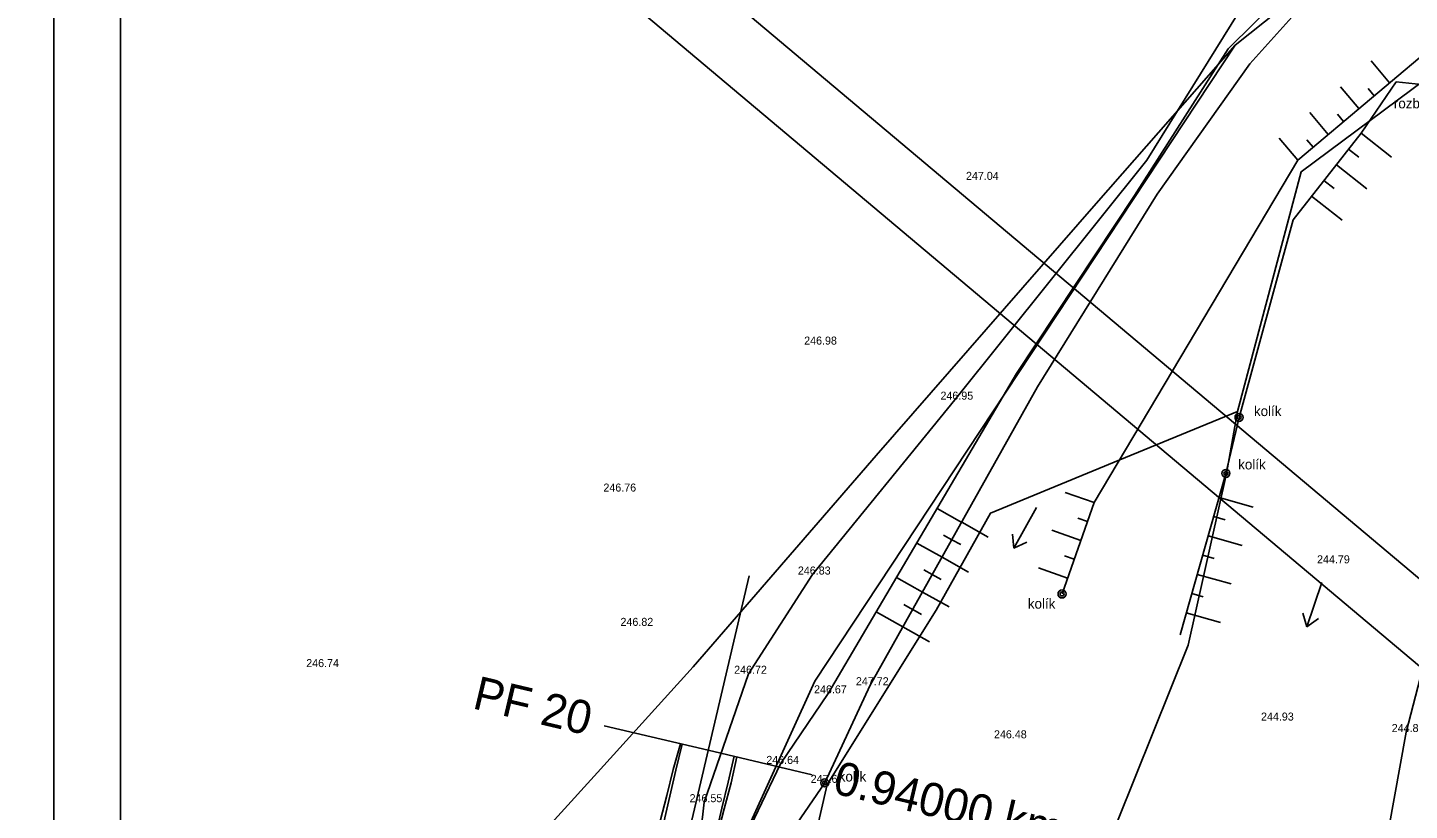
# Model space of a CAD drawing. Extents: x -555887 to -552101, y -1100251 to -1096546.
# Drawn here: x -554315.6 to -554212, y -1096894.5 to -1096835.8 of the extents above; entities that cross this region are included whole.
import ezdxf

# ---------------------------------------------------------------- set-up
doc = ezdxf.new("R2010")
doc.units = 0
for name, color, linetype in [('PARCELY_VHO', 7, 'Continuous'), ('POLYGONY_SITUACE_PF', 7, 'Continuous'), ('POLYGONY_SITUACE_PF_POPISY', 7, 'Continuous'), ('POLYGONY_SITUACE_PO', 7, 'Continuous'), ('ram_VC2', 7, 'Continuous'), ('ram_VC6', 7, 'Continuous'), ('Výškopis', 7, 'Continuous'), ('ZSST', 7, 'Continuous'), ('zájem', 7, 'Continuous')]:
    doc.layers.add(name, color=color, linetype=linetype)

msp = doc.modelspace()

# ---------------------------------------------------------------- linework, layer by layer
at = {"layer": 'PARCELY_VHO'}
for points in [[(-554130.46, -1097180.06), (-554159.17, -1097101.34), (-554159.64, -1097082.93), (-554163.72, -1097067.19), (-554173.74, -1097050.79), (-554190.63, -1097034.96), (-554197.16, -1097028.05), (-554217.46, -1096987.98), (-554225.33, -1096977.64), (-554234.21, -1096944.26), (-554236.99, -1096909.92), (-554235.22, -1096898.62), (-554228.6, -1096882.13), (-554225.73, -1096869.26), (-554224.9, -1096864.61), (-554220.11, -1096846.63), (-554200.4, -1096831.93), (-554179.17, -1096807.62), (-554142.08, -1096773.53), (-554110.69, -1096747.36), (-554089.18, -1096729.49)], [(-554235.26, -1097250.21), (-554222.33, -1097095.1), (-554222.18, -1097088.53), (-554223.59, -1097078.8), (-554226.63, -1097069.37), (-554233.34, -1097058.26), (-554245.88, -1097042.06), (-554250.33, -1097033.26), (-554252.75, -1097025.27), (-554253.64, -1097013.94), (-554251.14, -1096944.55), (-554252.47, -1096936.15), (-554254.99, -1096928.04), (-554262.23, -1096914.12), (-554265.12, -1096907.97), (-554264.18, -1096901.52), (-554256.59, -1096884.82), (-554225.08, -1096837.14), (-554208.2, -1096823.7)], [(-554200.4, -1096831.93), (-554220.11, -1096846.63), (-554224.9, -1096864.61), (-554233.29, -1096868.06), (-554243.42, -1096872.22), (-554247.48, -1096879.5), (-554255.66, -1096892.57), (-554260.45, -1096913.44), (-554248.68, -1096931.61), (-554247, -1096951.09), (-554248.74, -1096969.23), (-554247.82, -1097012.49), (-554234.69, -1097042.48), (-554228.63, -1097050.04), (-554218.79, -1097074.22), (-554216.52, -1097103.52), (-554219.47, -1097120.44), (-554219.42, -1097159.44)]]:
    msp.add_lwpolyline(points, dxfattribs=at)
at = {"layer": 'POLYGONY_SITUACE_PF'}
for p, q in [((-554272.37, -1096888.17), (-554264.58, -1096890)), ((-554264.58, -1096890), (-554256.79, -1096891.84))]:
    msp.add_line(p, q, dxfattribs=at)
at = {"layer": 'POLYGONY_SITUACE_PO'}
for p, q in [((-554268.72, -1096907.59), (-554261.5, -1096876.93)), ((-554267.2, -1096891.44), (-554266.65, -1096889.52)), ((-554266.99, -1096891.49), (-554266.53, -1096889.55)), ((-554266.99, -1096891.49), (-554266.53, -1096889.55)), ((-554263.09, -1096892.41), (-554262.63, -1096890.46)), ((-554263.09, -1096892.41), (-554262.63, -1096890.46)), ((-554262.86, -1096892.46), (-554262.43, -1096890.51)), ((-554267.67, -1096893.39), (-554267.2, -1096891.44)), ((-554267.44, -1096893.44), (-554266.99, -1096891.49)), ((-554267.44, -1096893.44), (-554266.99, -1096891.49)), ((-554263.55, -1096894.36), (-554263.09, -1096892.41)), ((-554263.55, -1096894.36), (-554263.09, -1096892.41)), ((-554263.39, -1096894.39), (-554262.86, -1096892.46)), ((-554268.17, -1096895.32), (-554267.67, -1096893.39)), ((-554267.9, -1096895.39), (-554267.44, -1096893.44)), ((-554267.9, -1096895.39), (-554267.44, -1096893.44)), ((-554264.01, -1096896.3), (-554263.55, -1096894.36)), ((-554264.01, -1096896.3), (-554263.55, -1096894.36)), ((-554263.88, -1096896.33), (-554263.39, -1096894.39))]:
    msp.add_line(p, q, dxfattribs=at)
at = {"layer": 'ram_VC2'}
for points in [[(-554114.88, -1096958.27), (-554342.13, -1096767.04), (-555018.18, -1097570.44), (-554790.93, -1097761.67)], [(-554121.93, -1096958.88), (-554341.52, -1096774.09), (-555011.14, -1097569.84), (-554791.54, -1097754.63)]]:
    msp.add_lwpolyline(points, close=True, dxfattribs=at)
for points in [[(-554114.88, -1096958.27), (-554342.13, -1096767.04), (-555018.18, -1097570.44), (-554790.93, -1097761.67), (-554114.88, -1096958.27)], [(-554791.54, -1097754.63), (-555011.14, -1097569.84), (-554341.52, -1096774.09), (-554121.93, -1096958.88), (-554791.54, -1097754.63)]]:
    msp.add_lwpolyline(points, dxfattribs=at)
at = {"layer": 'ram_VC6'}
for points in [[(-553956.64, -1096765.72), (-554313.64, -1096765.72), (-554313.64, -1097395.72), (-553956.64, -1097395.72)], [(-553961.64, -1096770.72), (-554308.64, -1096770.72), (-554308.64, -1097390.72), (-553961.64, -1097390.72)]]:
    msp.add_lwpolyline(points, close=True, dxfattribs=at)
for points in [[(-553956.64, -1096765.72), (-554313.64, -1096765.72), (-554313.64, -1097395.72), (-553956.64, -1097395.72), (-553956.64, -1096765.72)], [(-553956.64, -1096765.72), (-554313.64, -1096765.72), (-554313.64, -1097395.72), (-553956.64, -1097395.72), (-553956.64, -1096765.72)], [(-553961.64, -1097390.72), (-554308.64, -1097390.72), (-554308.64, -1096770.72), (-553961.64, -1096770.72), (-553961.64, -1097390.72)], [(-553961.64, -1097185.72), (-553961.64, -1097390.72), (-554308.64, -1097390.72), (-554308.64, -1096770.72), (-553961.64, -1096770.72), (-553961.64, -1096975.72), (-553961.64, -1097185.72)]]:
    msp.add_lwpolyline(points, dxfattribs=at)
at = {"layer": 'ZSST'}
for p, q in [((-554213.5, -1096839.96), (-554214.88, -1096838.32)), ((-554215.79, -1096841.9), (-554217.17, -1096840.26)), ((-554215.63, -1096843.75), (-554212.99, -1096839.89)), ((-554214.64, -1096840.93), (-554215.1, -1096840.38)), ((-554218.09, -1096843.83), (-554219.47, -1096842.19)), ((-554216.94, -1096842.86), (-554217.4, -1096842.32)), ((-554215.63, -1096843.75), (-554213.35, -1096845.54)), ((-554220.38, -1096845.76), (-554221.76, -1096844.12)), ((-554219.23, -1096844.79), (-554219.69, -1096844.25)), ((-554216.56, -1096844.93), (-554215.8, -1096845.53)), ((-554217.48, -1096846.11), (-554215.2, -1096847.9)), ((-554218.41, -1096847.29), (-554217.65, -1096847.89)), ((-554219.34, -1096848.47), (-554217.05, -1096850.26)), ((-554235.64, -1096871.44), (-554237.82, -1096870.67)), ((-554239.95, -1096871.8), (-554241.65, -1096874.86)), ((-554235.64, -1096871.44), (-554235.64, -1096871.44)), ((-554226.27, -1096871.05), (-554223.72, -1096871.77)), ((-554245.57, -1096872.92), (-554247.41, -1096871.88)), ((-554245.57, -1096872.91), (-554243.58, -1096874.03)), ((-554236.14, -1096872.85), (-554236.86, -1096872.6)), ((-554226.68, -1096872.49), (-554225.83, -1096872.73)), ((-554246.31, -1096874.22), (-554246.93, -1096873.87)), ((-554241.65, -1096874.86), (-554241.77, -1096873.8)), ((-554236.64, -1096874.27), (-554238.82, -1096873.5)), ((-554227.09, -1096873.93), (-554224.54, -1096874.66)), ((-554247.04, -1096875.53), (-554248.94, -1096874.47)), ((-554246.31, -1096874.22), (-554245.64, -1096874.59)), ((-554240.69, -1096874.4), (-554241.65, -1096874.86)), ((-554247.04, -1096875.53), (-554245.05, -1096876.65)), ((-554237.13, -1096875.68), (-554237.86, -1096875.43)), ((-554227.5, -1096875.37), (-554226.65, -1096875.62)), ((-554248.51, -1096878.15), (-554250.46, -1096877.05)), ((-554247.78, -1096876.84), (-554248.42, -1096876.48)), ((-554247.78, -1096876.84), (-554247.11, -1096877.21)), ((-554237.63, -1096877.1), (-554239.81, -1096876.33)), ((-554227.91, -1096876.82), (-554225.36, -1096877.54)), ((-554218.56, -1096877.44), (-554219.7, -1096880.75)), ((-554249.25, -1096879.46), (-554249.9, -1096879.09)), ((-554248.51, -1096878.15), (-554246.52, -1096879.26)), ((-554228.32, -1096878.26), (-554227.47, -1096878.5)), ((-554249.98, -1096880.76), (-554251.98, -1096879.64)), ((-554249.24, -1096879.45), (-554248.58, -1096879.83)), ((-554228.73, -1096879.7), (-554226.18, -1096880.43)), ((-554219.7, -1096880.75), (-554220, -1096879.73)), ((-554218.83, -1096880.13), (-554219.7, -1096880.75)), ((-554249.98, -1096880.76), (-554247.99, -1096881.88))]:
    msp.add_line(p, q, dxfattribs=at)
for points in [[(-554252.3, -1096962.91), (-554251.89, -1096947.46), (-554254.33, -1096933.96), (-554258.67, -1096923.35), (-554264.63, -1096912.03), (-554266.17, -1096905.46), (-554264.87, -1096893.9), (-554261.55, -1096884.27), (-554256.75, -1096876.83), (-554246.08, -1096863.72), (-554231.7, -1096845.76), (-554223.08, -1096831.86), (-554218.37, -1096827.54), (-554210.29, -1096822.07), (-554198.72, -1096814.57), (-554189.47, -1096809.37), (-554178.38, -1096802.21), (-554170.29, -1096795.75), (-554158.02, -1096787.64), (-554138.36, -1096771.85), (-554116.97, -1096752.81), (-554099.76, -1096736.76), (-554079.01, -1096718.05)], [(-554188, -1096818.64), (-554188.82, -1096814.37), (-554190.64, -1096810.55), (-554203.49, -1096818.78), (-554212.9, -1096826.01), (-554219.76, -1096831.63), (-554225.59, -1096837.42), (-554232.61, -1096848.4), (-554241.45, -1096861.76), (-554255.58, -1096885.74), (-554259.15, -1096891.03), (-554264.18, -1096901.52), (-554262.23, -1096914.12), (-554254.91, -1096925), (-554250.45, -1096935.08), (-554250.08, -1096950.54), (-554252.3, -1096962.91)], [(-554248.75, -1096969.32), (-554248.83, -1096959.93), (-554247.06, -1096950.99), (-554246.71, -1096943.72), (-554248.72, -1096931.57), (-554260.49, -1096913.37), (-554262.48, -1096905.88), (-554262.15, -1096901.68), (-554255.84, -1096892.45), (-554252.43, -1096885.13), (-554239.88, -1096862.77), (-554230.92, -1096848.31), (-554223.97, -1096838.55), (-554218.79, -1096832.76), (-554212.02, -1096827.16), (-554202.06, -1096819.83), (-554190.67, -1096813.97), (-554190.64, -1096810.55)], [(-554197.77, -1096834.17), (-554197.55, -1096832.08), (-554195.86, -1096827.42), (-554203.8, -1096831.8), (-554220.38, -1096845.76)], [(-554212.99, -1096839.89), (-554209.21, -1096840.28), (-554208.27, -1096839.96), (-554205.15, -1096840.55), (-554205.63, -1096841.17), (-554202.65, -1096842.97)], [(-554229.2, -1096881.34), (-554225.76, -1096869.25), (-554224.78, -1096865.05), (-554220.72, -1096850.23), (-554215.63, -1096843.75)], [(-554238.05, -1096878.29), (-554235.64, -1096871.44), (-554220.38, -1096845.76)], [(-554189.44, -1097009.07), (-554189.29, -1097003.58), (-554192.09, -1096996.42), (-554196.79, -1096989.85), (-554203.75, -1096978.28), (-554211.03, -1096961.03), (-554216.96, -1096944.48), (-554220.11, -1096936.16), (-554213.34, -1096924.57), (-554209.99, -1096922.37), (-554215.63, -1096918.27), (-554219.45, -1096911.72), (-554215.85, -1096907.48), (-554214.43, -1096900.67), (-554212.25, -1096888.64), (-554208.26, -1096873.22), (-554195.25, -1096867.45)]]:
    msp.add_lwpolyline(points, dxfattribs=at)
for centre, radius in [((-554224.78, -1096865.05), 0.3), ((-554224.78, -1096865.05), 0.15), ((-554225.76, -1096869.25), 0.3), ((-554225.76, -1096869.25), 0.15), ((-554238.05, -1096878.29), 0.3), ((-554238.05, -1096878.29), 0.15), ((-554255.84, -1096892.45), 0.3), ((-554255.84, -1096892.45), 0.15)]:
    msp.add_circle(centre, radius, dxfattribs=at)
at = {"layer": 'zájem'}
for points in [[(-554089.18, -1096729.49), (-554110.69, -1096747.36), (-554142.08, -1096773.53), (-554179.17, -1096807.62), (-554205.78, -1096822.41), (-554208.2, -1096823.7), (-554225.08, -1096837.14), (-554235.5, -1096849), (-554251.97, -1096867.91), (-554264.55, -1096882.42), (-554265.7, -1096883.76), (-554272.88, -1096891.67), (-554281.79, -1096901.5), (-554289.93, -1096910.44), (-554329.92, -1096954.43), (-554333.96, -1096958.92), (-554536.43, -1097182.04)], [(-554536.43, -1097182.04), (-554333.96, -1096958.92), (-554329.92, -1096954.43), (-554289.93, -1096910.44), (-554281.79, -1096901.5), (-554272.88, -1096891.67), (-554265.7, -1096883.76), (-554264.55, -1096882.42), (-554251.97, -1096867.91), (-554235.5, -1096849), (-554225.08, -1096837.14), (-554208.2, -1096823.7), (-554205.78, -1096822.41), (-554179.17, -1096807.62), (-554142.08, -1096773.53), (-554110.69, -1096747.36), (-554089.18, -1096729.49)], [(-554197.16, -1097028.05), (-554217.46, -1096987.98), (-554225.33, -1096977.64), (-554234.21, -1096944.26), (-554236.99, -1096909.92), (-554235.22, -1096898.62), (-554228.6, -1096882.13), (-554225.73, -1096869.26), (-554224.9, -1096864.61), (-554233.29, -1096868.06), (-554243.42, -1096872.22), (-554247.48, -1096879.5), (-554255.66, -1096892.57), (-554260.45, -1096913.44), (-554248.68, -1096931.61), (-554247, -1096951.09), (-554248.74, -1096969.23), (-554247.82, -1097012.49)], [(-554247.82, -1097012.49), (-554248.74, -1096969.23), (-554247, -1096951.09), (-554248.68, -1096931.61), (-554260.45, -1096913.44), (-554255.66, -1096892.57), (-554247.48, -1096879.5), (-554243.42, -1096872.22), (-554233.29, -1096868.06), (-554224.9, -1096864.61), (-554225.73, -1096869.26), (-554228.6, -1096882.13), (-554235.22, -1096898.62), (-554236.99, -1096909.92), (-554234.21, -1096944.26), (-554225.33, -1096977.64), (-554217.46, -1096987.98), (-554197.16, -1097028.05)]]:
    msp.add_lwpolyline(points, dxfattribs=at)

# ---------------------------------------------------------------- texts
at = {"layer": 'POLYGONY_SITUACE_PF_POPISY'}
for s, p in [('PF 20', (-554282.33, -1096886.85)), ('0.94000 km', (-554255.32, -1096893.21))]:
    msp.add_text(s, height=2.5, rotation=346.7443, dxfattribs=at).set_placement(p)
at = {"layer": 'Výškopis'}
for s, p in [('247.04', (-554245.25, -1096847.24)), ('246.98', (-554257.38, -1096859.59)), ('246.95', (-554247.16, -1096863.72)), ('246.76', (-554272.43, -1096870.61)), ('244.79', (-554218.93, -1096875.99)), ('246.83', (-554257.85, -1096876.83)), ('246.82', (-554271.15, -1096880.68)), ('246.74', (-554294.71, -1096883.77)), ('246.72', (-554262.63, -1096884.27)), ('246.67', (-554256.64, -1096885.74)), ('247.72', (-554253.5, -1096885.13)), ('244.93', (-554223.13, -1096887.78)), ('244.80', (-554213.33, -1096888.64)), ('246.48', (-554243.15, -1096889.11)), ('246.64', (-554260.22, -1096891.03)), ('247.67', (-554256.89, -1096892.45)), ('246.55', (-554265.97, -1096893.9))]:
    msp.add_text(s, height=0.6, dxfattribs=at).set_placement(p)
at = {"layer": 'ZSST'}
for s, p in [('rozbitý beton', (-554213.17, -1096841.88)), ('kolík', (-554223.66, -1096864.95)), ('kolík', (-554224.84, -1096868.95)), ('kolík', (-554240.61, -1096879.39)), ('kolík', (-554254.79, -1096892.35))]:
    msp.add_text(s, height=0.75, dxfattribs=at).set_placement(p)

doc.saveas('drawing.dxf')
